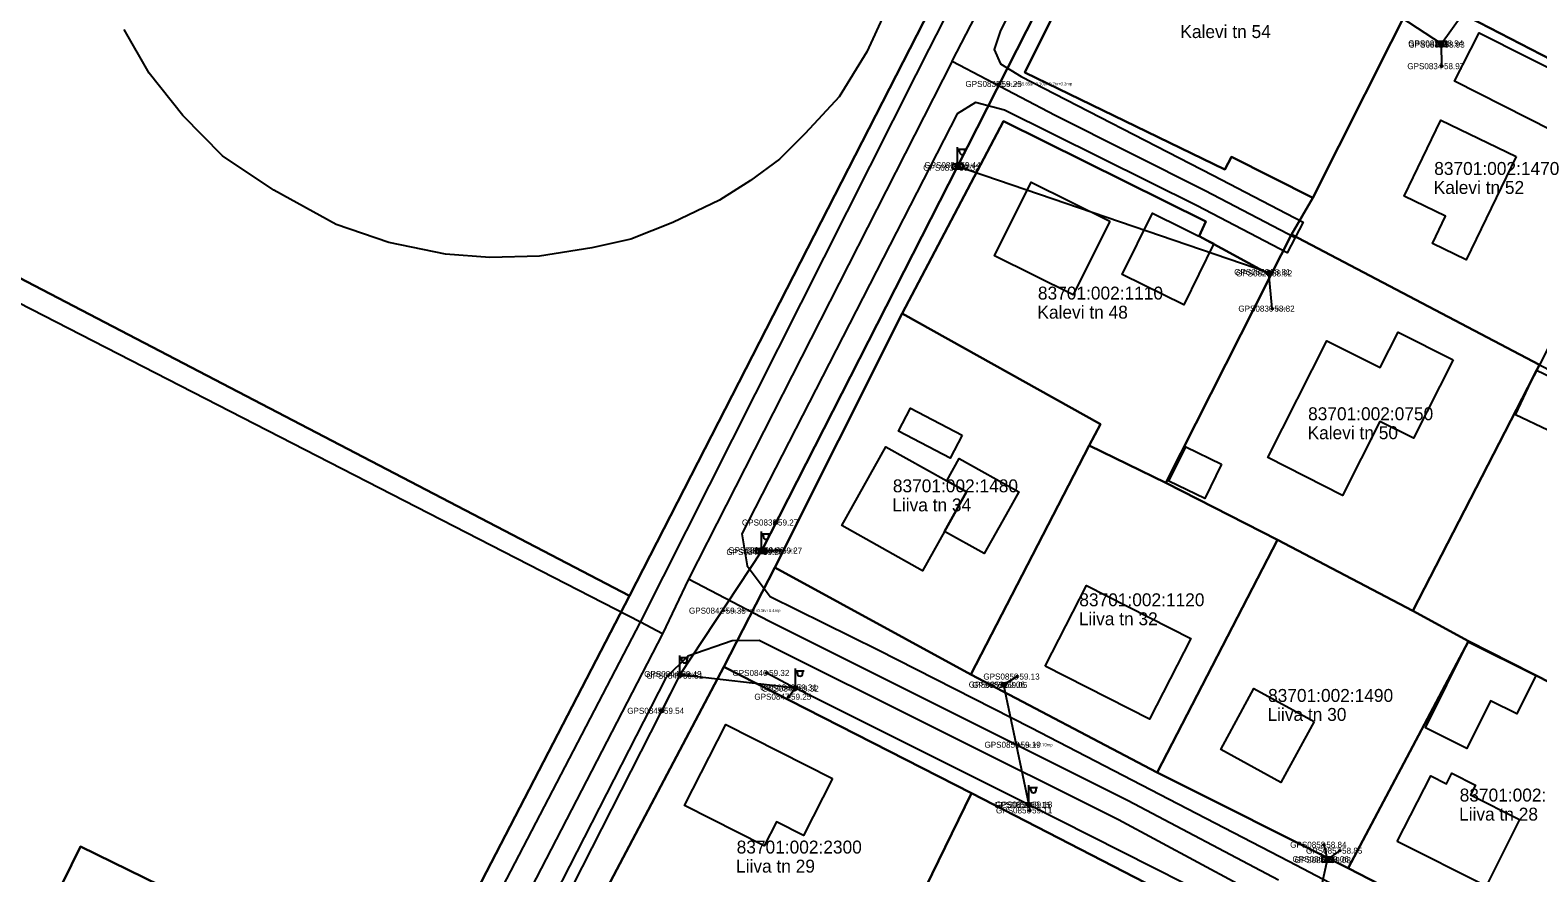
# Model space of a CAD drawing. Extents: x 580119 to 583377, y 6518915 to 6520820.
# Drawn here: x 581488.7 to 581663.4, y 6520357.7 to 6520455.4 of the extents above; entities that cross this region are included whole.
import ezdxf

# ---------------------------------------------------------------- set-up
doc = ezdxf.new("R2010")
doc.units = 0
for name, color, linetype in [('ELRAJATISMP', 7, 'Continuous'), ('Hoone Elu- või ühiskondlik hoone', 7, 'Continuous'), ('Hoone Kõrval- või tootmishoone', 7, 'Continuous'), ('L_AADRESS', 7, 'Continuous'), ('MAAMUDEL', 7, 'Continuous'), ('MOOTKORG-EH2000', 7, 'Continuous'), ('MOOTMPUNKT', 7, 'Continuous'), ('MOOTNR', 7, 'Continuous'), ('MPOHULIIN', 7, 'Continuous'), ('PIIR', 7, 'Continuous'), ('POST', 7, 'Continuous'), ('Rippe kõrgus', 7, 'Continuous'), ('SIOHULIIN', 7, 'Continuous'), ('Tee Liiklusala', 7, 'Continuous'), ('Tee Rada Püsikate', 7, 'Continuous'), ('Tee Sport', 7, 'Continuous'), ('Tee Tänav Kruuskate', 7, 'Continuous'), ('Tee Tänav Püsikate', 7, 'Continuous'), ('TUNNUS', 7, 'Continuous')]:
    doc.layers.add(name, color=color, linetype=linetype)

msp = doc.modelspace()

# ---------------------------------------------------------------- linework, layer by layer
at = {"layer": 'ELRAJATISMP'}
for p, q in [((581652.11, 6520454.07), (581652.11, 6520453.47)), ((581652.38, 6520454.07), (581652.38, 6520453.47)), ((581596.03, 6520439.86), (581596.03, 6520439.26)), ((581596.3, 6520439.86), (581596.3, 6520439.26)), ((581573.29, 6520395.26), (581573.29, 6520394.67)), ((581573.56, 6520395.26), (581573.56, 6520394.67)), ((581638.89, 6520359.5), (581638.89, 6520358.9)), ((581639.16, 6520359.5), (581639.16, 6520358.9))]:
    msp.add_line(p, q, dxfattribs=at)
for points in [[(581651.65, 6520454.07), (581652.84, 6520454.07), (581652.84, 6520453.47), (581651.65, 6520453.47)], [(581595.57, 6520439.86), (581596.76, 6520439.86), (581596.76, 6520439.26), (581595.57, 6520439.26)], [(581572.83, 6520395.26), (581574.02, 6520395.26), (581574.02, 6520394.67), (581572.83, 6520394.67)], [(581638.42, 6520359.5), (581639.62, 6520359.5), (581639.62, 6520358.9), (581638.42, 6520358.9)]]:
    msp.add_lwpolyline(points, close=True, dxfattribs=at)
at = {"layer": 'Hoone Elu- või ühiskondlik hoone'}
for points in [[(581660.91, 6520440.73), (581655.11, 6520428.75), (581651.19, 6520430.64), (581652.71, 6520433.78), (581647.91, 6520436.1), (581652.18, 6520444.94)], [(581613.81, 6520433.21), (581609.57, 6520424.66), (581600.45, 6520429.19), (581604.69, 6520437.75)], [(581653.58, 6520417.15), (581648.99, 6520408.06), (581645.11, 6520410.01), (581640.78, 6520401.43), (581632.13, 6520405.8), (581638.96, 6520419.36), (581645.15, 6520416.25), (581647.22, 6520420.35)], [(581597.21, 6520401.83), (581594.65, 6520397.24), (581592.11, 6520392.69), (581582.73, 6520397.92), (581587.83, 6520407.07), (581594.91, 6520403.13)], [(581606.32, 6520381.64), (581611.09, 6520390.99), (581623.18, 6520384.83), (581618.41, 6520375.48)], [(581637.49, 6520375.2), (581633.62, 6520368.15), (581626.65, 6520371.96), (581630.51, 6520379.02)], [(581581.67, 6520368.59), (581578.32, 6520361.98), (581575.16, 6520363.57), (581573.76, 6520360.79), (581564.53, 6520365.45), (581569.29, 6520374.87)], [(581647.12, 6520361.29), (581651.01, 6520368.92), (581652.81, 6520368), (581653.45, 6520369.23), (581656.19, 6520367.84), (581655.59, 6520366.69), (581661.27, 6520363.83), (581657.4, 6520356.12)]]:
    msp.add_lwpolyline(points, close=True, dxfattribs=at)
at = {"layer": 'Hoone Kõrval- või tootmishoone'}
for points in [[(581667.88, 6520449.36), (581665.02, 6520443.73), (581653.75, 6520449.45), (581656.6, 6520455.07)], [(581625.87, 6520430.62), (581622.37, 6520423.52), (581615.23, 6520427.03), (581618.74, 6520434.13)], [(581674.5, 6520410.58), (581672.05, 6520405.43), (581660.8, 6520410.78), (581663.24, 6520415.93)], [(581596.71, 6520408.41), (581595.32, 6520405.73), (581589.3, 6520408.86), (581590.69, 6520411.53)], [(581626.75, 6520405.05), (581624.8, 6520401.07), (581620.66, 6520403.09), (581622.61, 6520407.07)], [(581601.79, 6520399.22), (581599.26, 6520394.68), (581594.65, 6520397.24), (581597.21, 6520401.83), (581594.91, 6520403.13), (581596.34, 6520405.7), (581603.26, 6520401.85)], [(581663.18, 6520380.54), (581660.98, 6520376.11), (581657.94, 6520377.62), (581655.19, 6520372.07), (581650.37, 6520374.47), (581655.32, 6520384.44)]]:
    msp.add_lwpolyline(points, close=True, dxfattribs=at)
at = {"layer": 'MOOTMPUNKT'}
for centre in [(581652.16, 6520453.84), (581652.33, 6520453.69), (581652.27, 6520451.19), (581600.99, 6520449.13), (581596.1, 6520439.41), (581596.23, 6520439.72), (581632.14, 6520427.33), (581632.34, 6520427.16), (581632.62, 6520423.08), (581575.09, 6520398.28), (581573.36, 6520394.86), (581573.5, 6520395.07), (581575.55, 6520395.03), (581569.02, 6520388.06), (581574.06, 6520380.84), (581563.9, 6520380.71), (581564.08, 6520380.52), (581577.26, 6520379.15), (581577.47, 6520379.02), (581601.37, 6520379.49), (581601.64, 6520379.44), (581603.07, 6520380.42), (581576.6, 6520378.08), (581561.87, 6520376.45), (581603.2, 6520372.51), (581604.32, 6520365.54), (581604.53, 6520365.58), (581604.53, 6520364.9), (581638.63, 6520360.92), (581640.46, 6520360.23), (581638.9, 6520359.25), (581639.14, 6520359.14)]:
    msp.add_circle(centre, 0.1, dxfattribs=at)
at = {"layer": 'MPOHULIIN'}
for p, q in [((581652.25, 6520453.77), (581615.6, 6520477.81)), ((581652.27, 6520451.19), (581652.25, 6520453.77)), ((581639.02, 6520359.2), (581638.63, 6520360.92))]:
    msp.add_line(p, q, dxfattribs=at)
for points in [[(581575.55, 6520395.03), (581573.43, 6520394.97), (581596.17, 6520439.56), (581615.6, 6520477.81), (581632.42, 6520511.16), (581647.95, 6520541.63)], [(581632.62, 6520423.08), (581632.24, 6520427.24), (581596.17, 6520439.56)], [(581573.43, 6520394.97), (581563.99, 6520380.62), (581550.36, 6520353.89), (581536.13, 6520325.71), (581518.2, 6520290.77), (581498.96, 6520253.33), (581478.9, 6520214.22), (581458.59, 6520174.68)], [(581636.81, 6520349.16), (581604.43, 6520365.56), (581577.37, 6520379.09), (581563.99, 6520380.62)], [(581603.07, 6520380.42), (581601.5, 6520379.46), (581604.43, 6520365.56), (581604.53, 6520364.9)], [(581577.37, 6520379.09), (581576.6, 6520378.08)], [(581610.57, 6520323.92), (581636.81, 6520349.16), (581639.02, 6520359.2), (581640.46, 6520360.23)]]:
    msp.add_lwpolyline(points, dxfattribs=at)
at = {"layer": 'PIIR'}
for points in [[(581449.24, 6520446.57), (581543.55, 6520653.33), (581657.24, 6520583.27), (581558.12, 6520389.79)], [(581662.65, 6520485.99), (581665.21, 6520491.23), (581694.15, 6520476.35), (581692.6, 6520473.48), (581678.18, 6520445.13), (581649.42, 6520460)], [(581617.04, 6520476.8), (581649.42, 6520460), (581637.33, 6520435.93), (581627.9, 6520440.67), (581627.14, 6520439.21), (581603.95, 6520450.44)], [(581637.33, 6520435.93), (581649.42, 6520460), (581678.18, 6520445.13), (581663.6, 6520416.58), (581634.87, 6520431.66)], [(581601.5, 6520444.8), (581624.92, 6520433.19), (581624.14, 6520431.49), (581632.47, 6520426.94), (581620.3, 6520402.87), (581611.42, 6520407.22), (581612.74, 6520409.7), (581589.74, 6520422.5)], [(581632.47, 6520426.94), (581634.87, 6520431.66), (581663.6, 6520416.58), (581648.92, 6520388.04), (581633.24, 6520396.27), (581620.3, 6520402.87)], [(581589.74, 6520422.5), (581612.74, 6520409.7), (581611.42, 6520407.22), (581597.7, 6520380.66), (581574.97, 6520393.06)], [(581648.92, 6520388.04), (581663.6, 6520416.58), (581692.57, 6520401.72), (581690.07, 6520397.32), (581677.65, 6520373.21), (581655.37, 6520384.54)], [(581611.42, 6520407.22), (581620.3, 6520402.87), (581633.24, 6520396.27), (581619.31, 6520369.31), (581597.7, 6520380.66)], [(581633.24, 6520396.27), (581648.92, 6520388.04), (581655.37, 6520384.54), (581641.44, 6520358.2), (581619.31, 6520369.31)], [(581655.37, 6520384.54), (581677.65, 6520373.21), (581663.75, 6520346.68), (581641.44, 6520358.2)], [(581569.06, 6520381.55), (581597.76, 6520366.89), (581583.28, 6520337.17), (581553.75, 6520352.5)], [(581583.28, 6520337.17), (581597.76, 6520366.89), (581626.79, 6520351.93), (581609.05, 6520322), (581582.45, 6520335.59)], [(581500.71, 6520277.24), (581462.65, 6520295.82), (581494.52, 6520360.71), (581533.26, 6520341.75)]]:
    msp.add_lwpolyline(points, close=True, dxfattribs=at)
for points in [[(581400.45, 6520092.33), (581500.71, 6520277.24), (581533.26, 6520341.75), (581558.12, 6520389.79), (581657.24, 6520583.27)], [(581617.04, 6520476.8), (581603.95, 6520450.44), (581627.14, 6520439.21), (581627.9, 6520440.67), (581637.33, 6520435.93), (581634.87, 6520431.66), (581632.47, 6520426.94), (581624.14, 6520431.49), (581624.92, 6520433.19), (581601.5, 6520444.8), (581589.74, 6520422.5), (581574.97, 6520393.06), (581569.06, 6520381.55), (581553.75, 6520352.5)], [(581384.33, 6520418.25), (581405.05, 6520409.44), (581419.35, 6520443.1), (581449.24, 6520446.57), (581558.12, 6520389.79), (581533.26, 6520341.75), (581494.52, 6520360.71), (581462.65, 6520295.82), (581500.71, 6520277.24), (581400.45, 6520092.33)], [(581691.15, 6520319.03), (581661.06, 6520334.72), (581632.23, 6520349), (581621.05, 6520327.16), (581622.75, 6520326.21), (581618.23, 6520317.33), (581613.67, 6520319.49), (581609.05, 6520322), (581626.79, 6520351.93), (581597.76, 6520366.89), (581569.06, 6520381.55), (581574.97, 6520393.06), (581597.7, 6520380.66), (581619.31, 6520369.31), (581641.44, 6520358.2), (581663.75, 6520346.68)]]:
    msp.add_lwpolyline(points, dxfattribs=at)
at = {"layer": 'POST'}
for p, q in [((581596.17, 6520439.81), (581596.17, 6520441.81)), ((581596.17, 6520441.56), (581597.17, 6520441.56)), ((581596.39, 6520441.24), (581596.39, 6520441.56)), ((581597.01, 6520441.24), (581597.01, 6520441.56)), ((581596.17, 6520439.56), (581596.17, 6520439.56)), ((581573.43, 6520395.22), (581573.43, 6520397.22)), ((581573.43, 6520396.97), (581574.43, 6520396.97)), ((581573.65, 6520396.65), (581573.65, 6520396.97)), ((581574.27, 6520396.65), (581574.27, 6520396.97)), ((581573.43, 6520394.97), (581573.43, 6520394.97)), ((581563.99, 6520380.87), (581563.99, 6520382.87)), ((581563.99, 6520382.62), (581564.99, 6520382.62)), ((581564.22, 6520382.3), (581564.22, 6520382.62)), ((581564.83, 6520382.3), (581564.83, 6520382.62)), ((581577.37, 6520379.34), (581577.37, 6520381.34)), ((581577.37, 6520381.09), (581578.37, 6520381.09)), ((581577.6, 6520380.77), (581577.6, 6520381.09)), ((581578.21, 6520380.77), (581578.21, 6520381.09)), ((581563.99, 6520380.62), (581563.99, 6520380.62)), ((581577.37, 6520379.09), (581577.37, 6520379.09)), ((581604.43, 6520365.81), (581604.43, 6520367.81)), ((581604.43, 6520367.56), (581605.43, 6520367.56)), ((581604.65, 6520367.24), (581604.65, 6520367.56)), ((581605.27, 6520367.24), (581605.27, 6520367.56)), ((581604.43, 6520365.56), (581604.43, 6520365.56))]:
    msp.add_line(p, q, dxfattribs=at)
for points in [[(581654.6, 6520457.05), (581652.25, 6520453.77)], [(581575.09, 6520398.28), (581573.43, 6520394.97)], [(581563.99, 6520380.62), (581561.87, 6520376.45)], [(581574.06, 6520380.84), (581577.37, 6520379.09)]]:
    msp.add_lwpolyline(points, dxfattribs=at)
for centre, radius in [((581652.25, 6520453.77), 0.25), ((581596.17, 6520439.56), 0.25), ((581632.24, 6520427.24), 0.25), ((581575.09, 6520398.28), 0.2), ((581573.43, 6520394.97), 0.25), ((581563.99, 6520380.62), 0.25), ((581574.06, 6520380.84), 0.125), ((581574.06, 6520380.84), 0.105), ((581574.06, 6520380.84), 0.0851), ((581574.06, 6520380.84), 0.0651), ((581574.06, 6520380.84), 0.0451), ((581574.06, 6520380.84), 0.0251), ((581574.06, 6520380.84), 0.00511), ((581577.37, 6520379.09), 0.25), ((581601.5, 6520379.46), 0.25), ((581561.87, 6520376.45), 0.2), ((581604.43, 6520365.56), 0.25), ((581639.02, 6520359.2), 0.25)]:
    msp.add_circle(centre, radius, dxfattribs=at)
for centre in [(581596.7, 6520441.24), (581573.96, 6520396.65), (581564.52, 6520382.3), (581577.9, 6520380.77), (581604.96, 6520367.24)]:
    msp.add_arc(centre, 0.306, 180, 0, dxfattribs=at)
at = {"layer": 'SIOHULIIN'}
msp.add_lwpolyline([(581637.45, 6520518.52), (581632.42, 6520511.16), (581615.6, 6520477.81), (581596.17, 6520439.56), (581573.43, 6520394.97)], dxfattribs=at)
at = {"layer": 'Tee Liiklusala'}
for points in [[(581372.37, 6520277.77), (581412.75, 6520255.44), (581444.02, 6520238.01), (581474.39, 6520221.23), (581513.33, 6520297.97), (581534.24, 6520338.35), (581559.43, 6520386.73), (581591.38, 6520450.18), (581592.88, 6520453.16), (581609.8, 6520486.3), (581623.7, 6520512.67), (581636.83, 6520537.65), (581653.69, 6520569.75), (581656.07, 6520574.59), (581657.42, 6520577.86), (581657.31, 6520580.54), (581656.47, 6520584.5), (581655.72, 6520587.99), (581655.58, 6520589.38), (581654.54, 6520590.67), (581652.74, 6520592.05), (581631.26, 6520605.03)], [(581626.78, 6520505.9), (581601.14, 6520455.32), (581600.41, 6520453.14), (581601.14, 6520451.45), (581603.54, 6520449.99), (581625.76, 6520438.56), (581636.2, 6520433.09), (581635.27, 6520431.32), (581634.34, 6520429.55), (581623.94, 6520435), (581601.6, 6520446.07), (581598.23, 6520446.98), (581596.12, 6520445.68), (581571.14, 6520396.98), (581571.79, 6520393.25), (581574.44, 6520389.7), (581586.97, 6520383.5), (581604.66, 6520374.53), (581634.54, 6520359.01), (581694.54, 6520327.56)], [(581628.59, 6520356.4), (581614.8, 6520363.79), (581573.15, 6520384.61), (581570.02, 6520384.56), (581564.89, 6520382.77), (581562.36, 6520380.26), (581521.08, 6520299.59)]]:
    msp.add_lwpolyline(points, dxfattribs=at)
at = {"layer": 'Tee Rada Püsikate'}
msp.add_lwpolyline([(581561.96, 6520385.36), (581559.43, 6520386.73), (581445.53, 6520445.19), (581438.96, 6520448.57)], dxfattribs=at)
at = {"layer": 'Tee Sport'}
msp.add_lwpolyline([(581642.4, 6520576.12), (581585.64, 6520452.86), (581582.45, 6520447.62), (581578.48, 6520443.4), (581575.51, 6520440.42), (581572.15, 6520437.93), (581568.55, 6520435.67), (581563.17, 6520433.07), (581558.28, 6520431.14), (581553.76, 6520430.11), (581547.71, 6520429.18), (581541.97, 6520429), (581536.8, 6520429.4), (581530.23, 6520430.74), (581524.16, 6520432.82), (581516.91, 6520436.8), (581510.98, 6520440.8), (581506.37, 6520445.46), (581502.49, 6520450.39), (581499.57, 6520455.46)], dxfattribs=at)
at = {"layer": 'Tee Tänav Kruuskate'}
msp.add_lwpolyline([(581595.55, 6520451.78), (581607.48, 6520445.5), (581624.85, 6520436.78), (581635.27, 6520431.32)], dxfattribs=at)
at = {"layer": 'Tee Tänav Püsikate'}
for points in [[(581595.55, 6520451.78), (581626.35, 6520511.27)], [(581595.55, 6520451.78), (581564.98, 6520391.73)], [(581564.98, 6520391.73), (581561.96, 6520385.36)], [(581633.37, 6520356.8), (581615.94, 6520366.02), (581574.29, 6520386.83), (581564.98, 6520391.73)], [(581561.96, 6520385.36), (581516.22, 6520296.85)]]:
    msp.add_lwpolyline(points, dxfattribs=at)

# ---------------------------------------------------------------- texts
at = {"layer": 'L_AADRESS'}
for s, p in [('Kalevi tn 54', (581621.98, 6520454.45)), ('Kalevi tn 52', (581651.34, 6520436.38)), ('Kalevi tn 48', (581605.41, 6520421.92)), ('Kalevi tn 50', (581636.72, 6520407.94)), ('Liiva tn 34', (581588.59, 6520399.57)), ('Liiva tn 32', (581610.21, 6520386.37)), ('Liiva tn 30', (581632.08, 6520375.28)), ('Liiva tn 28', (581654.28, 6520363.72)), ('Liiva tn 29', (581570.49, 6520357.69))]:
    msp.add_text(s, height=1.5, dxfattribs=at).set_placement(p)
at = {"layer": 'MAAMUDEL'}
for s, p in [(' kaabel', (581596.1, 6520439.23)), (' kaabel', (581596.23, 6520439.54)), (' mp_ohl', (581632.62, 6520422.91)), (' kaabel', (581573.36, 6520394.69)), (' kaabel', (581573.5, 6520394.89)), (' mp_ohl', (581575.55, 6520394.86)), (' kaabel', (581563.9, 6520380.54)), (' kaabel', (581564.08, 6520380.35))]:
    msp.add_text(s, height=0.35, dxfattribs=at).set_placement(p)
at = {"layer": 'MOOTKORG-EH2000'}
for s, p in [(' 58.94', (581652.16, 6520453.49)), (' 58.93', (581652.33, 6520453.34)), (' 58.97', (581652.27, 6520450.84)), (' 59.25', (581600.99, 6520448.78)), (' 59.32', (581596.1, 6520439.06)), (' 59.44', (581596.23, 6520439.37)), (' 58.81', (581632.14, 6520426.98)), (' 58.92', (581632.34, 6520426.81)), (' 58.82', (581632.62, 6520422.73)), (' 59.27', (581575.09, 6520397.93)), (' 59.29', (581573.36, 6520394.51)), (' 59.29', (581573.5, 6520394.72)), (' 59.27', (581575.55, 6520394.68)), (' 59.35', (581569.02, 6520387.71)), (' 59.49', (581563.9, 6520380.36)), (' 59.51', (581564.08, 6520380.17)), (' 59.32', (581574.06, 6520380.49)), (' 59.31', (581577.26, 6520378.8)), (' 59.32', (581577.47, 6520378.67)), (' 59.06', (581601.37, 6520379.14)), (' 59.05', (581601.64, 6520379.09)), (' 59.13', (581603.07, 6520380.07)), (' 59.25', (581576.6, 6520377.73)), (' 59.54', (581561.87, 6520376.1)), (' 59.19', (581603.2, 6520372.16)), (' 59.15', (581604.32, 6520365.19)), (' 59.11', (581604.53, 6520364.55)), (' 59.18', (581604.53, 6520365.23)), (' 58.84', (581638.63, 6520360.57)), (' 58.85', (581640.46, 6520359.88)), (' 59.06', (581638.9, 6520358.9)), (' 59.08', (581639.14, 6520358.79))]:
    msp.add_text(s, height=0.7, dxfattribs=at).set_placement(p)
at = {"layer": 'MOOTNR'}
for s, p in [('GPS0831 ', (581648.38, 6520453.49)), ('GPS0832 ', (581648.41, 6520453.34)), ('GPS0834 ', (581648.28, 6520450.84)), ('GPS0835 ', (581597.07, 6520448.78)), ('GPS0837 ', (581592.18, 6520439.06)), ('GPS0836 ', (581592.31, 6520439.37)), ('GPS0829 ', (581628.22, 6520426.98)), ('GPS0828 ', (581628.42, 6520426.81)), ('GPS0830 ', (581628.7, 6520422.73)), ('GPS0838 ', (581571.17, 6520397.93)), ('GPS0840 ', (581569.37, 6520394.51)), ('GPS0839 ', (581569.58, 6520394.72)), ('GPS0841 ', (581571.7, 6520394.68)), ('GPS0842 ', (581565.03, 6520387.71)), ('GPS0844 ', (581559.84, 6520380.36)), ('GPS0843 ', (581560.09, 6520380.17)), ('GPS0846 ', (581570.07, 6520380.49)), ('GPS0848 ', (581573.27, 6520378.8)), ('GPS0849 ', (581573.48, 6520378.67)), ('GPS0852 ', (581597.45, 6520379.14)), ('GPS0851 ', (581597.86, 6520379.09)), ('GPS0850 ', (581599.15, 6520380.07)), ('GPS0847 ', (581572.61, 6520377.73)), ('GPS0845 ', (581557.88, 6520376.1)), ('GPS0853 ', (581599.28, 6520372.16)), ('GPS0855 ', (581600.4, 6520365.19)), ('GPS0854 ', (581600.54, 6520365.23)), ('GPS0856 ', (581600.61, 6520364.55)), ('GPS0858 ', (581634.71, 6520360.57)), ('GPS0857 ', (581636.54, 6520359.88)), ('GPS0860 ', (581634.98, 6520358.9)), ('GPS0859 ', (581635.22, 6520358.79))]:
    msp.add_text(s, height=0.7, dxfattribs=at).set_placement(p)
at = {"layer": 'Rippe kõrgus'}
for s, p in [(' el_mp_ohl55.85si+0.10si+0.7tv+0.2mp', (581600.99, 6520448.96)), (' el_mp_ohl7.30si+0.3tv+0.4mp', (581569.02, 6520387.89)), (' el_mp_ohl7.70mp', (581603.2, 6520372.33))]:
    msp.add_text(s, height=0.35, dxfattribs=at).set_placement(p)
at = {"layer": 'TUNNUS'}
for s, p in [('83701:002:1470', (581651.4, 6520438.58)), ('83701:002:1110', (581605.47, 6520424.13)), ('83701:002:0750', (581636.78, 6520410.14)), ('83701:002:1480', (581588.66, 6520401.78)), ('83701:002:1120', (581610.27, 6520388.57)), ('83701:002:1490', (581632.14, 6520377.48)), ('83701:002:1130', (581654.35, 6520365.93)), ('83701:002:2300', (581570.56, 6520359.9))]:
    msp.add_text(s, height=1.5, dxfattribs=at).set_placement(p)

doc.saveas('drawing.dxf')
